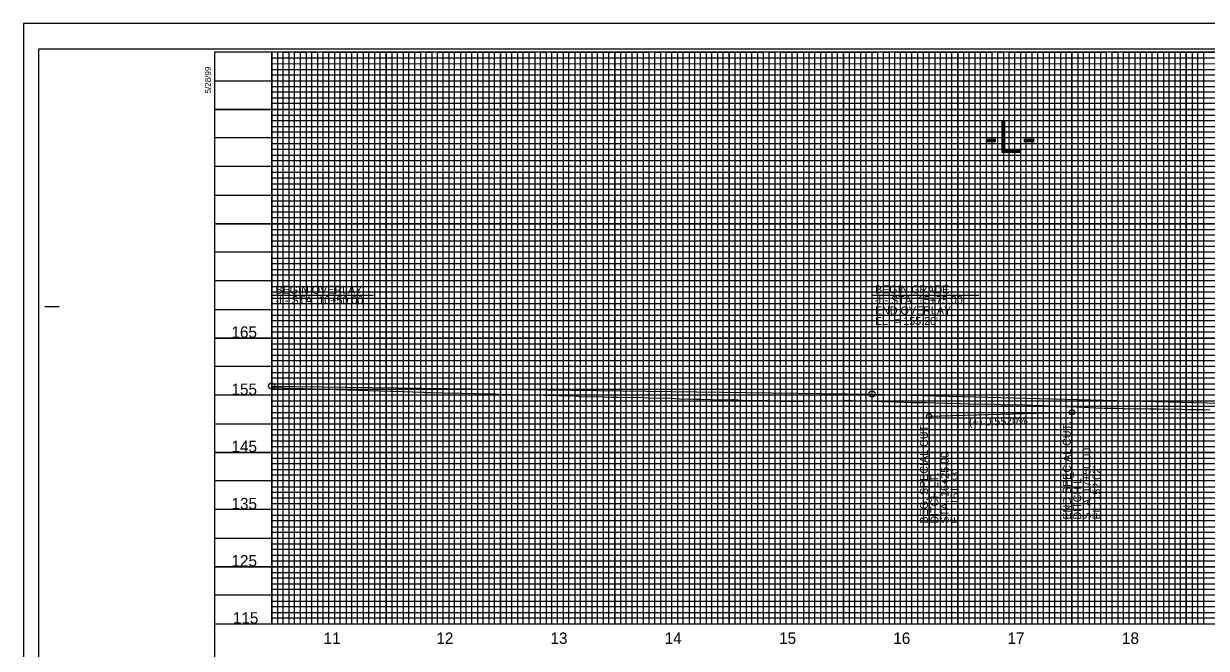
# Model space of a CAD drawing. Extents: x 573468 to 580768, y -57414 to -51768.
# Drawn here: x 578678 to 579713, y -52460 to -51914 of the extents above; entities that cross this region are included whole.
import ezdxf

# ---------------------------------------------------------------- set-up
doc = ezdxf.new("R2010")
doc.units = 0
for name, color, linetype in [('Exist Vertical Profile Ground Line', 7, 'Continuous'), ('Exist Vertical Profile Horizontal Axis Label Major', 7, 'Continuous'), ('Exist Vertical Profile Vertical Axis Label', 7, 'Continuous'), ('Prop Grid Mask', 7, 'Continuous'), ('Prop PFL Text', 7, 'Continuous'), ('Prop Vertical Profile Ditch Grade Left', 7, 'Continuous'), ('Prop Vertical Profile Ditch Grade Left Label', 7, 'Continuous'), ('Prop Vertical Profile Grade', 7, 'Continuous'), ('Prop VPI Label', 7, 'Continuous'), ('Sheet Cutting Line CELL', 7, 'Continuous'), ('Sheet DOT Grid CELL', 7, 'Continuous'), ('Sheet Layout Profile Border Port 1', 7, 'Continuous'), ('Sheet Plot Border Inside CELL', 7, 'Continuous'), ('Sheet Plot Border Outside CELL', 7, 'Continuous'), ('Sheet Profile CELL', 7, 'Continuous'), ('Sheet Profile Grid Major CELL', 7, 'Continuous'), ('Sheet Profile Grid Middle CELL', 7, 'Continuous'), ('Sheet Profile Grid Minor CELL', 7, 'Continuous')]:
    doc.layers.add(name, color=color, linetype=linetype)

msp = doc.modelspace()

# ---------------------------------------------------------------- linework, layer by layer
at = {"layer": 'Exist Vertical Profile Ground Line'}
msp.add_lwpolyline([(578895.2, -52231.7), (578913.2, -52232.3), (578913.8, -52232.3), (578931.8, -52232.9), (578943, -52233.1), (578943.5, -52233.1), (578969.6, -52234), (578970.9, -52234), (578999.4, -52235), (579001.7, -52235), (579027.8, -52235.7), (579028.2, -52235.7), (579029.1, -52236.1), (579034, -52236), (579057.2, -52236.6), (579058.2, -52236.5), (579061.7, -52236.8), (579085.2, -52237.4), (579087.9, -52237.3), (579090.6, -52237.3), (579093.7, -52237.7), (579117.6, -52238.3), (579120.2, -52238.1), (579131.1, -52238.3), (579133.3, -52238.4), (579159.4, -52239), (579162, -52239.1), (579164.1, -52239.5), (579185.8, -52240), (579192.7, -52240.2), (579197.4, -52240.3), (579220.9, -52240.4), (579225, -52240.8), (579245.2, -52241.2), (579251.6, -52241.6), (579263.6, -52241.9), (579269.7, -52241.9), (579289.3, -52242.4), (579297.6, -52242.2), (579299, -52242.1), (579306.7, -52242.8), (579321.8, -52243.2), (579329.2, -52242.9), (579331.1, -52243.5), (579349.6, -52243.9), (579357.8, -52243.6), (579360.4, -52243.6), (579372.8, -52243.4), (579395.4, -52243), (579403, -52243.2), (579423, -52243.8), (579428.9, -52244), (579433.3, -52244.1), (579455.5, -52244.8), (579460.7, -52244.9), (579467.9, -52245), (579474.8, -52245.2), (579497.1, -52245.7), (579497.7, -52245.7), (579505.6, -52245.9), (579527.7, -52246.4), (579532.9, -52246.6), (579555.4, -52247), (579560.4, -52247.1), (579560.9, -52247.2), (579583.5, -52248.2), (579590.3, -52248.4), (579593.3, -52248.5), (579616, -52249.6), (579623.3, -52249.8), (579634, -52249.9), (579640.8, -52250.1), (579663.3, -52250.4), (579668.8, -52250.5), (579691.2, -52250.8), (579696.5, -52250.9), (579709.4, -52251.1), (579715.8, -52251.3)], dxfattribs=at)
at = {"layer": 'Prop Grid Mask'}
msp.add_lwpolyline([(579495.2, -51988.5), (579595.2, -51988.5), (579595.2, -52038.5), (579495.2, -52038.5)], close=True, dxfattribs=at)
at = {"layer": 'Prop PFL Text'}
for p, q in [((578895.2, -52151), (578895.2, -52230.5)), ((578895.2, -52151), (578984.1, -52151)), ((579420.2, -52150.9), (579420.2, -52237.5)), ((579420.2, -52150.9), (579513.6, -52150.9))]:
    msp.add_line(p, q, dxfattribs=at)
at = {"layer": 'Prop Vertical Profile Ditch Grade Left'}
msp.add_line((579470.2, -52256.9), (579595.2, -52253.4), dxfattribs=at)
at = {"layer": 'Prop Vertical Profile Ditch Grade Left Label'}
for p, q in [((579470.2, -52256.9), (579470.2, -52352.9)), ((579595.2, -52253.4), (579595.2, -52349.4))]:
    msp.add_line(p, q, dxfattribs=at)
for centre in [(579595.2, -52253.4), (579470.2, -52256.9)]:
    msp.add_circle(centre, 2.25, dxfattribs=at)
at = {"layer": 'Prop Vertical Profile Grade'}
for p, q in [((578895.2, -52230.5), (579420.2, -52237.5)), ((579420.2, -52237.5), (579935.2, -52251))]:
    msp.add_line(p, q, dxfattribs=at)
at = {"layer": 'Prop VPI Label'}
for centre in [(578895.2, -52230.5), (579420.2, -52237.5)]:
    msp.add_circle(centre, 2.75, dxfattribs=at)
at = {"layer": 'Sheet Cutting Line CELL'}
for p, q in [((580362.2, -51913.5), (578678.2, -51913.5)), ((578678.2, -51913.5), (578678.2, -53013.5))]:
    msp.add_line(p, q, dxfattribs=at)
at = {"layer": 'Sheet DOT Grid CELL'}
for p, q in [((578895.2, -52438.5), (578895.2, -51938.5)), ((578945.2, -52438.5), (578945.2, -51938.5)), ((578995.2, -52438.5), (578995.2, -51938.5)), ((579045.2, -52438.5), (579045.2, -51938.5)), ((579095.2, -52438.5), (579095.2, -51938.5)), ((579145.2, -52438.5), (579145.2, -51938.5)), ((579195.2, -52438.5), (579195.2, -51938.5)), ((579245.2, -52438.5), (579245.2, -51938.5)), ((579295.2, -52438.5), (579295.2, -51938.5)), ((579345.2, -52438.5), (579345.2, -51938.5)), ((579395.2, -52438.5), (579395.2, -51938.5)), ((579445.2, -52438.5), (579445.2, -51938.5)), ((579495.2, -52438.5), (579495.2, -51938.5)), ((579545.2, -52438.5), (579545.2, -51938.5)), ((579595.2, -52438.5), (579595.2, -51938.5)), ((579645.2, -52438.5), (579645.2, -51938.5)), ((579695.2, -52438.5), (579695.2, -51938.5)), ((580145.2, -51988.5), (578845.2, -51988.5)), ((580145.2, -52038.5), (578845.2, -52038.5)), ((580345.2, -52088.5), (578845.2, -52088.5)), ((580345.2, -52138.5), (578845.2, -52138.5)), ((580345.2, -52188.5), (578845.2, -52188.5)), ((580345.2, -52238.5), (578845.2, -52238.5)), ((580345.2, -52288.5), (578845.2, -52288.5)), ((580345.2, -52338.5), (578845.2, -52338.5)), ((580345.2, -52388.5), (578845.2, -52388.5))]:
    msp.add_line(p, q, dxfattribs=at)
at = {"layer": 'Sheet Layout Profile Border Port 1'}
msp.add_lwpolyline([(578895.2, -51938.5), (578895.2, -52438.5), (580295.2, -52438.5), (580295.2, -52076.1), (580145.2, -52076.1), (580145.2, -51938.5)], close=True, dxfattribs=at)
at = {"layer": 'Sheet Plot Border Inside CELL'}
msp.add_lwpolyline([(578691.2, -52991.1), (580357.7, -52991.1), (580357.7, -51936), (578691.2, -51936)], close=True, dxfattribs=at)
at = {"layer": 'Sheet Plot Border Outside CELL'}
msp.add_lwpolyline([(578678.2, -53013.5), (580362.2, -53013.5), (580362.2, -51913.5), (578678.2, -51913.5)], close=True, dxfattribs=at)
at = {"layer": 'Sheet Profile CELL'}
for p, q in [((578696.7, -52161), (578709.2, -52161)), ((578845.2, -52438.5), (580345.2, -52438.5))]:
    msp.add_line(p, q, dxfattribs=at)
msp.add_lwpolyline([(580345.2, -51938.5), (578845.2, -51938.5), (578845.2, -52988.5), (580345.2, -52988.5)], close=True, dxfattribs=at)
at = {"layer": 'Sheet Profile Grid Major CELL'}
for points in [[(578895.2, -51938.5), (578895.2, -52438.5), (578945.2, -52438.5), (578945.2, -51938.5), (578995.2, -51938.5), (578995.2, -52438.5), (579045.2, -52438.5), (579045.2, -51938.5), (579095.2, -51938.5), (579095.2, -52438.5), (579145.2, -52438.5), (579145.2, -51938.5), (579195.2, -51938.5), (579195.2, -52438.5), (579245.2, -52438.5), (579245.2, -51938.5), (579295.2, -51938.5), (579295.2, -52438.5), (579345.2, -52438.5), (579345.2, -51938.5), (579395.2, -51938.5), (579395.2, -52438.5), (579445.2, -52438.5), (579445.2, -51938.5), (579495.2, -51938.5), (579495.2, -52438.5), (579545.2, -52438.5), (579545.2, -51938.5), (579595.2, -51938.5), (579595.2, -52438.5), (579645.2, -52438.5), (579645.2, -51938.5), (579695.2, -51938.5), (579695.2, -52438.5), (579745.2, -52438.5)], [(578845.2, -51988.5), (580145.2, -51988.5)], [(580145.2, -52038.5), (578845.2, -52038.5), (578845.2, -52088.5), (580345.2, -52088.5)], [(580345.2, -52138.5), (578845.2, -52138.5), (578845.2, -52188.5), (580345.2, -52188.5)], [(580345.2, -52238.5), (578845.2, -52238.5), (578845.2, -52288.5), (580345.2, -52288.5)], [(580345.2, -52338.5), (578845.2, -52338.5), (578845.2, -52338.5), (578845.2, -52388.5), (580345.2, -52388.5)]]:
    msp.add_lwpolyline(points, dxfattribs=at)
at = {"layer": 'Sheet Profile Grid Middle CELL'}
msp.add_line((578845.2, -51963.5), (580145.2, -51963.5), dxfattribs=at)
for points in [[(578920.2, -51938.5), (578920.2, -52438.5), (578970.2, -52438.5), (578970.2, -51938.5), (579020.2, -51938.5), (579020.2, -52438.5), (579070.2, -52438.5), (579070.2, -51938.5), (579120.2, -51938.5), (579120.2, -52438.5), (579170.2, -52438.5), (579170.2, -51938.5), (579220.2, -51938.5), (579220.2, -52438.5), (579270.2, -52438.5), (579270.2, -51938.5), (579320.2, -51938.5), (579320.2, -52438.5), (579370.2, -52438.5), (579370.2, -51938.5), (579420.2, -51938.5), (579420.2, -52438.5), (579470.2, -52438.5), (579470.2, -52438.5), (579470.2, -51938.5), (579520.2, -51938.5), (579520.2, -52438.5), (579570.2, -52438.5), (579570.2, -51938.5), (579620.2, -51938.5), (579620.2, -52438.5), (579670.2, -52438.5), (579670.2, -51938.5), (579720.2, -51938.5)], [(580145.2, -52013.5), (578845.2, -52013.5), (578845.2, -52063.5), (580145.2, -52063.5)], [(580345.2, -52113.5), (578845.2, -52113.5), (578845.2, -52163.5), (580170.2, -52163.5)], [(580345.2, -52213.5), (578845.2, -52213.5), (578845.2, -52263.5), (580345.2, -52263.5)], [(580345.2, -52313.5), (578845.2, -52313.5), (578845.2, -52363.5), (580345.2, -52363.5)], [(580345.2, -52413.5), (578845.2, -52413.5)]]:
    msp.add_lwpolyline(points, dxfattribs=at)
at = {"layer": 'Sheet Profile Grid Minor CELL'}
for p, q in [((578895.2, -51943.5), (580145.2, -51943.5)), ((578895.2, -51948.5), (578895.2, -51948.5)), ((580145.2, -51948.5), (578895.2, -51948.9)), ((578895.2, -51953.5), (580145.2, -51953.5)), ((580145.2, -52073.5), (578895.2, -52073.5)), ((580295.2, -52078.5), (578895.2, -52078.5)), ((580295.2, -52083.5), (578895.2, -52083.5)), ((578895.2, -52093.5), (580295.2, -52093.5)), ((580295.2, -52098.5), (578895.2, -52098.5)), ((578895.2, -52103.5), (580295.2, -52103.5)), ((580295.2, -52123.5), (578895.2, -52123.5)), ((578895.2, -52128.5), (580295.2, -52128.5)), ((580295.2, -52148.5), (578895.2, -52148.5)), ((578895.2, -52153.5), (580295.2, -52153.5)), ((580295.2, -52173.5), (578895.2, -52173.5)), ((578895.2, -52178.5), (580295.2, -52178.5)), ((580295.2, -52183.5), (578895.2, -52183.5)), ((578895.2, -52193.5), (580295.2, -52193.5)), ((580295.2, -52198.5), (578895.2, -52198.5)), ((578895.2, -52203.5), (580295.2, -52203.5)), ((580295.2, -52208.5), (578895.2, -52208.5)), ((578895.2, -52218.5), (580295.2, -52218.5)), ((580295.2, -52223.5), (578895.2, -52223.5)), ((578895.2, -52228.5), (580295.2, -52228.5)), ((580295.2, -52233.5), (578895.2, -52233.5)), ((578895.2, -52243.5), (580295.2, -52243.5)), ((580295.2, -52248.5), (578895.2, -52248.5)), ((578895.2, -52253.5), (580295.2, -52253.5)), ((580295.2, -52258.5), (578895.2, -52258.5)), ((578895.2, -52268.5), (580295.2, -52268.5)), ((580295.2, -52273.5), (578895.2, -52273.5)), ((578895.2, -52278.5), (580295.2, -52278.5)), ((580295.2, -52283.5), (578895.2, -52283.5)), ((578895.2, -52293.5), (580295.2, -52293.5)), ((580295.2, -52298.5), (578895.2, -52298.5)), ((578895.2, -52303.5), (580295.2, -52303.5)), ((580295.2, -52308.5), (578895.2, -52308.5)), ((578895.2, -52318.5), (580295.2, -52318.5)), ((580295.2, -52323.5), (578895.2, -52323.5)), ((580295.2, -52328.5), (578895.2, -52328.5)), ((580295.2, -52333.5), (578895.2, -52333.5)), ((578895.2, -52343.5), (580295.2, -52343.5)), ((580295.2, -52348.5), (578895.2, -52348.5)), ((578895.2, -52353.5), (580295.2, -52353.5)), ((580295.2, -52358.5), (578895.2, -52358.5)), ((578895.2, -52368.5), (580295.2, -52368.5)), ((580295.2, -52373.5), (578895.2, -52373.5)), ((578895.2, -52378.5), (580295.2, -52378.5)), ((580295.2, -52383.5), (578895.2, -52383.5)), ((578895.2, -52393.5), (580295.2, -52393.5)), ((580295.2, -52398.5), (578895.2, -52398.5)), ((578895.2, -52403.5), (580295.2, -52403.5)), ((580295.2, -52408.5), (578895.2, -52408.5)), ((578895.2, -52418.5), (580295.2, -52418.5)), ((580295.2, -52423.5), (578895.2, -52423.5)), ((578895.2, -52428.5), (580295.2, -52428.5))]:
    msp.add_line(p, q, dxfattribs=at)
for points in [[(578900.2, -51938.5), (578900.2, -52438.5), (578905.2, -52438.5), (578905.2, -51938.5), (578910.2, -51938.5), (578910.2, -52438.5), (578915.2, -52438.5), (578915.2, -51938.5), (578925.2, -51938.5), (578925.2, -52438.5), (578930.2, -52438.5), (578930.2, -51938.5), (578935.2, -51938.5), (578935.2, -52438.5), (578940.2, -52438.5), (578950.2, -52438.5), (578955.2, -52438.5), (578955.2, -51938.5), (578960.2, -51938.5), (578960.2, -52438.5), (578965.2, -52438.5), (578965.2, -51938.5), (578975.2, -51938.5), (578975.2, -52438.5), (578980.2, -52438.5), (578980.2, -51938.5), (578985.2, -51938.5), (578985.2, -52438.5), (578990.2, -52438.5), (578990.2, -51938.5), (579000.2, -51938.5), (579000.2, -52438.5), (579005.2, -52438.5), (579005.2, -51938.5), (579010.2, -51938.5), (579010.2, -52438.5), (579015.2, -52438.5), (579015.2, -51938.5), (579025.2, -51938.5), (579025.2, -52438.5), (579030.2, -52438.5), (579030.2, -51938.5), (579035.2, -51938.5), (579035.2, -52438.5), (579040.2, -52438.5), (579040.2, -51938.5), (579050.2, -51938.5), (579050.2, -52438.5), (579055.2, -52438.5), (579055.2, -51938.5), (579060.2, -51938.5), (579060.2, -52438.5), (579065.2, -52438.5), (579065.2, -51938.5), (579075.2, -51938.5), (579075.2, -52438.5), (579080.2, -52438.5), (579080.2, -51938.5), (579085.2, -51938.5), (579085.2, -52438.5), (579090.2, -52438.5), (579090.2, -51938.5), (579100.2, -51938.5), (579100.2, -52438.5), (579105.2, -52438.5), (579105.2, -51938.5), (579110.2, -51938.5), (579110.2, -52438.5)], [(578940.2, -52438.5), (578940.2, -51938.5), (578950.2, -51938.5), (578950.2, -52438.5)], [(579110.2, -52438.5), (579115.2, -52438.5), (579115.2, -51938.5), (579125.2, -51938.5), (579125.2, -52438.5), (579130.2, -52438.5), (579130.2, -51938.5), (579135.2, -51938.5), (579135.2, -52438.5), (579140.2, -52438.5), (579140.2, -51938.5), (579150.2, -51938.5), (579150.2, -52438.5), (579155.2, -52438.5), (579155.2, -51938.5), (579160.2, -51938.5), (579160.2, -52438.5), (579165.2, -52438.5), (579165.2, -51938.5), (579175.2, -51938.5), (579175.2, -52438.5), (579180.2, -52438.5), (579180.2, -51938.5), (579185.2, -51938.5), (579185.2, -52438.5), (579190.2, -52438.5), (579190.2, -51938.5), (579200.2, -51938.5), (579200.2, -52438.5), (579205.2, -52438.5), (579205.2, -51938.5), (579210.2, -51938.5), (579210.2, -52438.5), (579215.2, -52438.5), (579215.2, -51938.5), (579225.2, -51938.5), (579225.2, -52438.5), (579230.2, -52438.5), (579230.2, -51938.5), (579235.2, -51938.5), (579235.2, -52438.5), (579240.2, -52438.5), (579240.2, -51938.5), (579250.2, -51938.5), (579250.2, -52438.5), (579255.2, -52438.5), (579255.2, -51938.5), (579260.2, -51938.5), (579260.2, -52438.5), (579265.2, -52438.5), (579265.2, -51938.5), (579275.2, -51938.5), (579275.2, -52438.5), (579280.2, -52438.5), (579280.2, -51938.5), (579285.2, -51938.5), (579285.2, -52438.5), (579290.2, -52438.5), (579290.2, -51938.5), (579300.2, -51938.5), (579300.2, -52438.5), (579305.2, -52438.5), (579305.2, -51938.5), (579310.2, -51938.5), (579310.2, -52438.5), (579315.2, -52438.5), (579315.2, -51938.5), (579325.2, -51938.5), (579325.2, -52438.5), (579330.2, -52438.5), (579330.2, -51938.5), (579335.2, -51938.5), (579335.2, -52438.5), (579340.2, -52438.5), (579340.2, -51938.5), (579350.2, -51938.5), (579350.2, -52438.5), (579355.2, -52438.5), (579355.2, -51938.5), (579360.2, -51938.5), (579360.2, -52438.5), (579365.2, -52438.5), (579365.2, -51938.5), (579375.2, -51938.5), (579375.2, -52438.5), (579380.2, -52438.5), (579380.2, -51938.5), (579385.2, -51938.5), (579385.2, -52438.5), (579390.2, -52438.5), (579390.2, -51938.5), (579400.2, -51938.5), (579400.2, -52438.5), (579405.2, -52438.5), (579405.2, -51938.5), (579410.2, -51938.5), (579410.2, -52438.5), (579415.2, -52438.5), (579415.2, -51938.5), (579425.2, -51938.5)], [(579425.2, -51938.5), (579425.2, -52438.5), (579430.2, -52438.5), (579430.2, -51938.5), (579435.2, -51938.5), (579435.2, -52438.5), (579440.2, -52438.5), (579440.2, -51938.5), (579450.2, -51938.5), (579450.2, -52438.5), (579455.2, -52438.5), (579455.2, -51938.5), (579460.2, -51938.5), (579460.2, -52438.5), (579465.2, -52438.5), (579465.2, -51938.5), (579475.2, -51938.5), (579475.2, -52438.5), (579480.2, -52438.5), (579480.2, -51938.5), (579485.2, -51938.5), (579485.2, -52438.5), (579490.2, -52438.5), (579490.2, -51938.5), (579500.2, -51938.5), (579500.2, -52438.5), (579505.2, -52438.5), (579505.2, -51938.5), (579510.2, -51938.5), (579510.2, -52438.5), (579515.2, -52438.5), (579515.2, -51938.5), (579525.2, -51938.5), (579525.2, -52438.5), (579530.2, -52438.5), (579530.2, -51938.5), (579535.2, -51938.5), (579535.2, -52438.5), (579540.2, -52438.5), (579540.2, -51938.5), (579550.2, -51938.5), (579550.2, -52438.5), (579550.2, -52438.5), (579555.2, -52438.5), (579555.2, -51938.5), (579560.2, -51938.5), (579560.2, -52438.5), (579565.2, -52438.5), (579565.2, -51938.5), (579575.2, -51938.5), (579575.2, -52438.5), (579580.2, -52438.5), (579580.2, -51938.5), (579585.2, -51938.5), (579585.2, -52438.5), (579590.2, -52438.5), (579590.2, -51938.5), (579600.2, -51938.5), (579600.2, -52438.5), (579605.2, -52438.5), (579605.2, -51938.5), (579610.2, -51938.5), (579610.2, -52438.5), (579615.2, -52438.5), (579615.2, -51938.5), (579625.2, -51938.5), (579625.2, -52438.5), (579630.2, -52438.5), (579630.2, -51938.5), (579635.2, -51938.5), (579635.2, -52438.5), (579640.2, -52438.5), (579640.2, -51938.5), (579650.2, -51938.5), (579650.2, -52438.5), (579655.2, -52438.5), (579655.2, -51938.5), (579660.2, -51938.5), (579660.2, -52438.5), (579665.2, -52438.5), (579665.2, -51938.5), (579675.2, -51938.5), (579675.2, -52438.5), (579680.2, -52438.5), (579680.2, -51938.5), (579685.2, -51938.5), (579685.2, -52438.5), (579690.2, -52438.5), (579690.2, -51938.5), (579700.2, -51938.5), (579700.2, -52438.5), (579704.9, -52438), (579705.2, -52438.5), (579705.2, -51938.5), (579710.2, -51938.5), (579710.2, -52438.5), (579715.2, -52438.5)], [(580145.2, -51958.5), (578895.2, -51958.5), (578895.2, -51968.5), (580145.2, -51968.5)], [(580145.2, -51973.5), (578895.2, -51973.5), (578895.2, -51978.5), (580145.2, -51978.5)], [(580145.2, -51983.5), (578895.2, -51983.5), (578895.2, -51993.5), (580145.2, -51993.5)], [(580145.2, -51998.5), (578895.2, -51998.5), (578895.2, -52003.5), (580145.2, -52003.5)], [(580145.2, -52008.5), (578895.2, -52008.5), (578895.2, -52018.5), (580145.2, -52018.5)], [(580145.2, -52023.5), (578895.2, -52023.5), (578895.2, -52028.5), (580145.2, -52028.5)], [(580145.2, -52033.5), (578895.2, -52033.5), (578895.2, -52043.5), (580145.2, -52043.5)], [(580145.2, -52048.6), (578895.3, -52048.6), (578895.3, -52053.5), (580145.2, -52053.5)], [(580145.2, -52058.5), (578895.2, -52058.5), (578895.2, -52068.5), (580145.2, -52068.5)], [(580295.2, -52108.5), (578895.2, -52108.5), (578895.2, -52118.5), (580295.2, -52118.5)], [(580295.2, -52133.5), (578895.2, -52133.5), (578895.2, -52143.5), (580295.2, -52143.5)], [(580295.2, -52158.5), (578895.2, -52158.5), (578895.2, -52168.5), (580295.2, -52168.5)], [(580295.2, -52433.5), (578895.2, -52433.5)]]:
    msp.add_lwpolyline(points, dxfattribs=at)

# ---------------------------------------------------------------- texts
at = {"layer": 'Exist Vertical Profile Horizontal Axis Label Major'}
for s, p in [('11', (578940.6, -52456)), ('12', (579039.2, -52456)), ('13', (579139, -52456)), ('14', (579238.9, -52456)), ('15', (579339, -52456)), ('16', (579438.9, -52456)), ('17', (579538.8, -52456)), ('18', (579638.9, -52456))]:
    msp.add_text(s, height=10, dxfattribs=at).set_placement(p)
at = {"layer": 'Exist Vertical Profile Vertical Axis Label'}
for s, p in [('165', (578860, -52188.3)), ('155', (578860, -52238.3)), ('145', (578860, -52288.3)), ('135', (578860, -52338.3)), ('125', (578860, -52388.3)), ('115', (578861.2, -52438.3))]:
    msp.add_text(s, height=10, dxfattribs=at).set_placement(p)
at = {"layer": 'Prop PFL Text'}
for s, height, p in [('-L-', 28.12, (579517.9, -52026.6)), ('BEGIN OVERLAY', 7, (578898.5, -52149.8)), ('BEGIN GRADE', 7, (579422.9, -52149.5)), ('-L- STA. 10+50.00', 7, (578898.5, -52158.9)), ('-L- STA. 15+75.00', 7, (579422.9, -52158.7)), ('END OVERLAY', 7, (579422.9, -52167.9)), ("EL. = 155.20'", 7, (579422.9, -52177.1))]:
    msp.add_text(s, height=height, dxfattribs=at).set_placement(p)
at = {"layer": 'Prop Vertical Profile Ditch Grade Left'}
for s, p in [("EL. 151.33'", (579496, -52350.8)), ("EL. 152.02'", (579620.2, -52347.3))]:
    msp.add_text(s, height=7, rotation=90, dxfattribs=at).set_placement(p)
at = {"layer": 'Prop Vertical Profile Ditch Grade Left Label'}
for s, rotation, p in [('BEG. SPECIAL CUT.', 90, (579469.2, -52350.8)), ('(+) 0.5520%', 1.581, (579505.2, -52265.5)), ('END SPECIAL CUT.', 90, (579594.2, -52347.3)), ('STA. 16+25.00', 90, (579487.3, -52350.8)), ('STA. 17+50.00', 90, (579611.4, -52347.3)), ('DITCH LT.', 90, (579603.3, -52347.3)), ('DITCH LT.', 90, (579478.3, -52350.8))]:
    msp.add_text(s, height=7, rotation=rotation, dxfattribs=at).set_placement(p)
at = {"layer": 'Sheet Profile CELL'}
msp.add_text('5/28/99', height=5.25, rotation=90, dxfattribs=at).set_placement((578842, -51974.6))

doc.saveas('drawing.dxf')
